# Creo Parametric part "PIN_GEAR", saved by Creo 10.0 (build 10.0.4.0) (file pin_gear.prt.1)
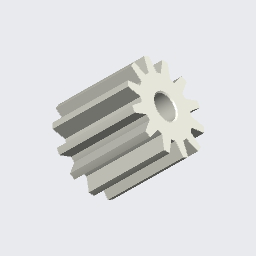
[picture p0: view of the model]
Units: millimeter Kilogram Sec (mmKs); MM, KILOGRAM, SECS

Created from: XX_SOLID_PART_MMKS_NEW_ABS.PRT

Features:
  1. datum plane "RIGHT"
  2. datum plane "TOP"
  3. datum plane "FRONT"
  4. coordinate system
  5. extrusion "Extrude 1"
  6. pattern "Pattern 1"
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
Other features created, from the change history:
  extruded cut "Extrude 2"
  extruded cut "Extrude 2 [2]"
  extruded cut "Extrude 2 [3]"
  extruded cut "Extrude 2 [4]"
  extruded cut "Extrude 2 [5]"
  extruded cut "Extrude 2 [6]"
  extruded cut "Extrude 2 [7]"
  extruded cut "Extrude 2 [8]"
  extruded cut "Extrude 2 [9]"
  extruded cut "Extrude 2 [10]"
  extruded cut "Extrude 2 [11]"
  extruded cut "Extrude 2 [12]"
  extruded cut "Extrude 3"
  chamfer "Chamfer 1"

Surfaces: 26 plane, 13 cylinder, 2 cone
